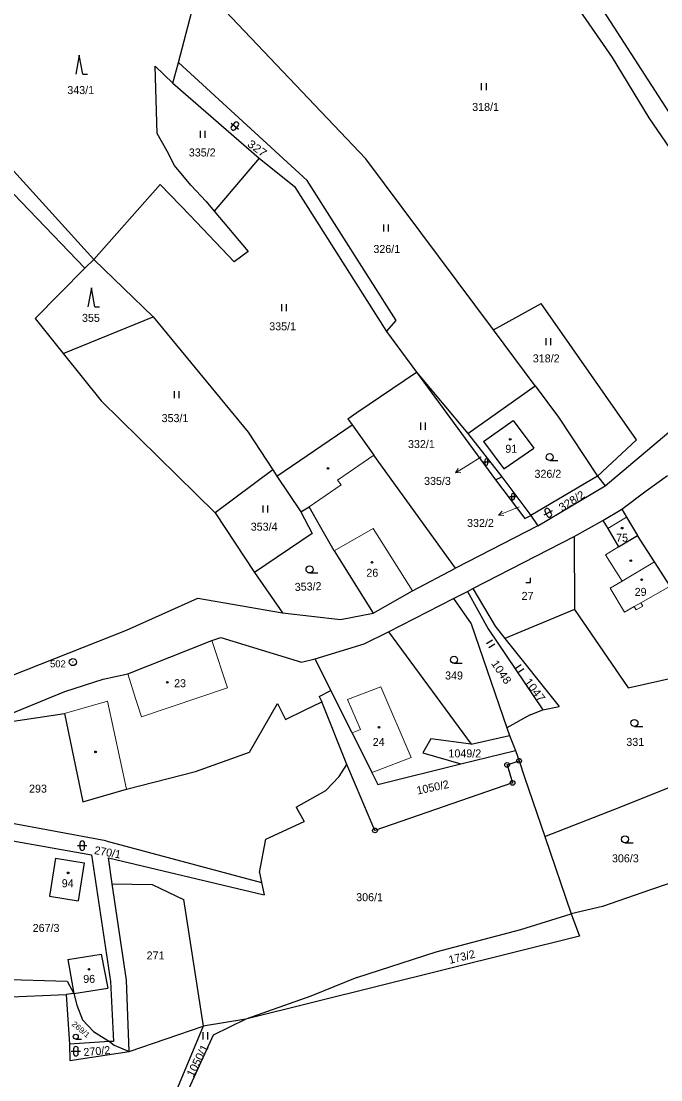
# Model space of a CAD drawing. Extents: x -744132 to -742433, y -984679 to -982287.
# Drawn here: x -742940.3 to -742804.5, y -984060.3 to -983835.5 of the extents above; entities that cross this region are included whole.
import ezdxf
from ezdxf.enums import TextEntityAlignment as Align

# ---------------------------------------------------------------- set-up
doc = ezdxf.new("R2010")
doc.units = 0
doc.header["$LTSCALE"] = 0.68
for name, color, linetype, lineweight in [('1', 7, 'Continuous', 25), ('3', 7, 'Continuous', 25), ('4', 7, 'Continuous', 13), ('5', 7, 'Continuous', 25), ('7', 7, 'Continuous', 13), ('8', 7, 'Continuous', 25)]:
    doc.layers.add(name, color=color, linetype=linetype, lineweight=lineweight)
doc.layers.add('2', color=7, linetype='Continuous')

msp = doc.modelspace()

# ---------------------------------------------------------------- linework, layer by layer
at = {"layer": '1'}
for p, q in [((-742906.93, -983844.32), (-742902.5, -983827.5)), ((-742902.5, -983827.5), (-742867.15, -983864.75)), ((-742822.34, -983832.43), (-742814.87, -983843.28)), ((-742911.42, -983859.4), (-742911.86, -983845.12)), ((-742911.86, -983845.12), (-742908.09, -983848.73)), ((-742908.09, -983848.73), (-742906.93, -983844.32)), ((-742879.59, -983869.35), (-742906.93, -983844.32)), ((-742908.09, -983848.73), (-742889.81, -983864.61)), ((-742957.02, -983850.8), (-742924.88, -983886.12)), ((-742958.15, -983855.44), (-742926.77, -983887.99)), ((-742909.3, -983863.15), (-742911.42, -983859.4)), ((-742907.74, -983866.2), (-742909.3, -983863.15)), ((-742889.81, -983864.61), (-742899.34, -983875.86)), ((-742889.81, -983864.61), (-742882.28, -983870.68)), ((-742840.06, -983901.1), (-742867.15, -983864.75)), ((-742904.28, -983870.35), (-742907.74, -983866.2)), ((-742860.67, -983899.08), (-742879.59, -983869.35)), ((-742924.88, -983886.12), (-742910.78, -983870.22)), ((-742910.78, -983870.22), (-742904.43, -983876.79)), ((-742901.02, -983873.87), (-742904.28, -983870.35)), ((-742882.28, -983870.68), (-742862.74, -983901.46)), ((-742901.02, -983873.87), (-742899.34, -983875.86)), ((-742895.09, -983886.66), (-742904.43, -983876.79)), ((-742899.34, -983875.86), (-742892.1, -983884.42)), ((-742892.1, -983884.42), (-742895.09, -983886.66)), ((-742926.77, -983887.99), (-742937.35, -983898.71)), ((-742924.88, -983886.12), (-742926.77, -983887.99)), ((-742924.88, -983886.12), (-742912.26, -983898.3)), ((-742840.06, -983901.1), (-742829.92, -983895.5)), ((-742809.68, -983924.43), (-742829.92, -983895.5)), ((-742937.35, -983898.71), (-742931.39, -983906.13)), ((-742931.39, -983906.13), (-742912.26, -983898.3)), ((-742912.26, -983898.3), (-742892.13, -983922.84)), ((-742862.74, -983901.46), (-742860.67, -983899.08)), ((-742862.74, -983901.46), (-742856.35, -983910.04)), ((-742831.22, -983912.97), (-742840.06, -983901.1)), ((-742931.39, -983906.13), (-742923.32, -983916.19)), ((-742869.02, -983918.66), (-742856.35, -983910.04)), ((-742856.35, -983910.04), (-742845.49, -983923.07)), ((-742856.35, -983910.04), (-742839.64, -983932.92)), ((-742845.49, -983923.07), (-742831.22, -983912.97)), ((-742831.22, -983912.97), (-742826.26, -983919.63)), ((-742923.32, -983916.19), (-742899.16, -983939.96)), ((-742870.96, -983919.98), (-742869.02, -983918.66)), ((-742886.03, -983932.15), (-742870.04, -983921.26)), ((-742870.96, -983919.98), (-742870.04, -983921.26)), ((-742870.04, -983921.26), (-742865.41, -983927.69)), ((-742842.15, -983924.76), (-742835.85, -983920.32)), ((-742835.85, -983920.32), (-742831.51, -983926.18)), ((-742826.26, -983919.63), (-742817.93, -983932.14)), ((-742816.35, -983934.19), (-742801.5, -983921.65)), ((-742892.13, -983922.84), (-742886.92, -983930.82)), ((-742845.49, -983923.07), (-742838.25, -983932.27)), ((-742842.15, -983924.76), (-742837.81, -983930.62)), ((-742837.81, -983930.62), (-742831.51, -983926.18)), ((-742817.93, -983932.14), (-742809.68, -983924.43)), ((-742848.1, -983951.72), (-742865.41, -983927.69)), ((-742886.92, -983930.82), (-742899.16, -983939.96)), ((-742886.92, -983930.82), (-742886.03, -983932.15)), ((-742886.03, -983932.15), (-742880.96, -983939.76)), ((-742839.64, -983932.92), (-742838.25, -983932.27)), ((-742839.64, -983932.92), (-742833.37, -983941.15)), ((-742838.25, -983932.27), (-742832.11, -983940.49)), ((-742817.93, -983932.14), (-742832.11, -983940.49)), ((-742817.93, -983932.14), (-742816.35, -983934.19)), ((-742807.62, -983935.3), (-742803.12, -983932.02)), ((-742830.62, -983942.7), (-742816.35, -983934.19)), ((-742812.81, -983939.15), (-742807.62, -983935.3)), ((-742880.96, -983939.76), (-742879.2, -983938.64)), ((-742880.96, -983939.76), (-742878.57, -983944.32)), ((-742876.73, -983943.06), (-742879.2, -983938.64)), ((-742816.81, -983941.55), (-742812.81, -983939.15)), ((-742812.81, -983939.15), (-742811.81, -983940.86)), ((-742899.16, -983939.96), (-742890.8, -983952.62)), ((-742833.37, -983941.15), (-742832.11, -983940.49)), ((-742832.11, -983940.49), (-742830.62, -983942.7)), ((-742822.88, -983944.99), (-742816.81, -983941.55)), ((-742816.81, -983941.55), (-742815.8, -983943.23)), ((-742811.81, -983940.86), (-742809.44, -983944.76)), ((-742873.89, -983948.03), (-742876.73, -983943.06)), ((-742830.62, -983942.7), (-742848.1, -983951.72)), ((-742815.8, -983943.23), (-742813.47, -983947.16)), ((-742844.42, -983956.03), (-742822.88, -983944.99)), ((-742822.88, -983944.99), (-742822.83, -983960.49)), ((-742813.47, -983947.16), (-742809.44, -983944.76)), ((-742805.85, -983950.36), (-742809.44, -983944.76)), ((-742873.89, -983948.03), (-742865.57, -983961.25)), ((-742802.53, -983955.53), (-742805.85, -983950.36)), ((-742857.26, -983956.51), (-742848.1, -983951.72)), ((-742865.57, -983961.25), (-742857.26, -983956.51)), ((-742848.52, -983958.12), (-742845.59, -983956.63)), ((-742845.59, -983956.63), (-742844.42, -983956.03)), ((-742845.59, -983956.63), (-742841.2, -983964.6)), ((-742844.42, -983956.03), (-742839.7, -983963.97)), ((-742917.94, -983964.86), (-742902.8, -983958.08)), ((-742902.8, -983958.08), (-742884.85, -983961.14)), ((-742862.31, -983965.19), (-742848.52, -983958.12)), ((-742848.52, -983958.12), (-742844.8, -983963.48)), ((-742884.85, -983961.14), (-742872.49, -983962.57)), ((-742872.49, -983962.57), (-742865.57, -983961.25)), ((-742822.83, -983960.49), (-742837.61, -983966.59)), ((-742822.83, -983960.49), (-742811.46, -983977.13)), ((-742844.8, -983963.48), (-742837.22, -983985.6)), ((-742839.7, -983963.97), (-742837.61, -983966.59)), ((-742945.7, -983975.78), (-742917.94, -983964.86)), ((-742899.86, -983967.08), (-742897.96, -983966.39)), ((-742897.96, -983966.39), (-742880.79, -983971.66)), ((-742867.51, -983967.72), (-742862.31, -983965.19)), ((-742862.31, -983965.19), (-742844.76, -983989.03)), ((-742841.2, -983964.6), (-742829.58, -983981.79)), ((-742837.61, -983966.59), (-742826.07, -983981.08)), ((-742917.66, -983974.14), (-742899.86, -983967.08)), ((-742877.9, -983970.94), (-742867.51, -983967.72)), ((-742880.79, -983971.66), (-742877.9, -983970.94)), ((-742874.54, -983977.66), (-742877.9, -983970.94)), ((-742931.01, -983977.85), (-742922.89, -983975.29)), ((-742922.89, -983975.29), (-742917.66, -983974.14)), ((-742811.46, -983977.13), (-742801.02, -983974.74)), ((-742954.25, -983987.39), (-742931.01, -983977.85)), ((-742877.04, -983978.95), (-742874.54, -983977.66)), ((-742870.05, -983986.66), (-742874.54, -983977.66)), ((-742880.19, -983981.86), (-742876.47, -983980.05)), ((-742877.04, -983978.95), (-742876.47, -983980.05)), ((-742871.15, -983993.39), (-742876.47, -983980.05)), ((-742943.85, -983984.44), (-742931.13, -983982.52)), ((-742931.13, -983982.52), (-742927.2, -984001.32)), ((-742891.86, -983990.76), (-742885.87, -983980.42)), ((-742885.87, -983980.42), (-742884.21, -983983.82)), ((-742884.21, -983983.82), (-742880.19, -983981.86)), ((-742832.26, -983982.86), (-742829.58, -983981.79)), ((-742829.58, -983981.79), (-742826.07, -983981.08)), ((-742832.26, -983982.86), (-742837.22, -983985.6)), ((-742870.05, -983986.66), (-742865.86, -983995.06)), ((-742837.22, -983985.6), (-742836.67, -983987.2)), ((-742853.34, -983987.9), (-742855.06, -983990.91)), ((-742844.76, -983989.03), (-742853.34, -983987.9)), ((-742844.76, -983989.03), (-742836.67, -983987.2)), ((-742836.67, -983987.2), (-742835.34, -983990.38)), ((-742903.31, -983994.88), (-742891.86, -983990.76)), ((-742855.06, -983990.91), (-742846.99, -983993.21)), ((-742846.99, -983993.21), (-742835.34, -983990.38)), ((-742835.34, -983990.38), (-742834.61, -983992.59)), ((-742872.82, -983995.92), (-742871.15, -983993.39)), ((-742869.15, -983998.19), (-742871.15, -983993.39)), ((-742864.57, -983997.65), (-742846.99, -983993.21)), ((-742837.15, -983993.45), (-742834.61, -983992.59)), ((-742837.15, -983993.45), (-742835.99, -983997.29)), ((-742834.61, -983992.59), (-742833.48, -983996.03)), ((-742917.96, -983998.64), (-742903.31, -983994.88)), ((-742875.66, -983998.9), (-742872.82, -983995.92)), ((-742865.86, -983995.06), (-742864.57, -983997.65)), ((-742833.48, -983996.03), (-742829.17, -984008.67)), ((-742812.62, -984002.25), (-742792.81, -983994.21)), ((-742865.2, -984007.38), (-742869.15, -983998.19)), ((-742835.99, -983997.29), (-742865.2, -984007.38)), ((-742927.2, -984001.32), (-742917.96, -983998.64)), ((-742881.96, -984002.42), (-742875.66, -983998.9)), ((-742881.96, -984002.42), (-742880.25, -984005.47)), ((-742829.17, -984008.67), (-742812.62, -984002.25)), ((-742922.34, -984009.55), (-742943.7, -984005.59)), ((-742888.35, -984009.24), (-742880.25, -984005.47)), ((-742889.73, -984016.32), (-742888.35, -984009.24)), ((-742829.17, -984008.67), (-742823.57, -984025.07)), ((-742942.1, -984009.55), (-742925.39, -984012.53)), ((-742922.34, -984009.55), (-742889.28, -984018.41)), ((-742933, -984013.29), (-742934.28, -984021.31)), ((-742933, -984013.29), (-742926.93, -984014.28)), ((-742925.39, -984012.53), (-742921.36, -984039.47)), ((-742921.8, -984013.22), (-742888.71, -984021.05)), ((-742920.98, -984018.74), (-742921.8, -984013.22)), ((-742786.48, -984013.12), (-742806.72, -984019.96)), ((-742926.93, -984014.28), (-742928.22, -984022.3)), ((-742889.73, -984016.32), (-742889.28, -984018.41)), ((-742889.28, -984018.41), (-742888.71, -984021.05)), ((-742917.95, -984039.15), (-742920.98, -984018.74)), ((-742920.98, -984018.74), (-742912.47, -984018.85)), ((-742912.47, -984018.85), (-742905.85, -984022.02)), ((-742806.72, -984019.96), (-742816.93, -984023.51)), ((-742934.28, -984021.31), (-742928.22, -984022.3)), ((-742905.85, -984022.02), (-742901.65, -984048.94)), ((-742834.23, -984028.38), (-742823.57, -984025.07)), ((-742816.93, -984023.51), (-742823.57, -984025.07)), ((-742823.57, -984025.07), (-742821.81, -984029.84)), ((-742852.2, -984033.16), (-742834.23, -984028.38)), ((-742821.81, -984029.84), (-742892.62, -984047.46)), ((-742930.4, -984034.77), (-742923.31, -984033.62)), ((-742923.31, -984033.62), (-742921.95, -984040.84)), ((-742869.08, -984038.63), (-742852.2, -984033.16)), ((-742930.4, -984034.77), (-742929.11, -984041.97)), ((-742869.08, -984038.63), (-742878.81, -984042.59)), ((-742945.1, -984038.93), (-742930.55, -984039.41)), ((-742930.55, -984039.41), (-742929.11, -984041.97)), ((-742929.11, -984041.97), (-742921.95, -984040.84)), ((-742921.36, -984039.47), (-742920.74, -984052.2)), ((-742917.4, -984054.33), (-742917.95, -984039.15)), ((-742944.15, -984042.77), (-742930.74, -984042.18)), ((-742929.11, -984041.97), (-742930.74, -984042.18)), ((-742930.74, -984042.18), (-742930.03, -984052.75)), ((-742929.11, -984041.97), (-742928.47, -984044.46)), ((-742878.81, -984042.59), (-742892.62, -984047.46)), ((-742928.47, -984044.46), (-742927.27, -984047.62)), ((-742927.27, -984047.62), (-742924.96, -984050.04)), ((-742892.62, -984047.46), (-742901.65, -984048.94)), ((-742892.62, -984047.46), (-742899.55, -984050.85)), ((-742917.4, -984054.33), (-742901.65, -984048.94)), ((-742901.65, -984048.94), (-742915.06, -984080.88)), ((-742921.57, -984052.19), (-742930.03, -984052.75)), ((-742899.55, -984050.85), (-742927.66, -984112.13)), ((-742924.96, -984050.04), (-742922.72, -984051.45)), ((-742922.72, -984051.45), (-742921.57, -984052.19)), ((-742921.57, -984052.19), (-742920.54, -984052.96)), ((-742920.74, -984052.2), (-742921.57, -984052.19)), ((-742930.03, -984052.75), (-742930, -984056.21)), ((-742930, -984056.21), (-742917.4, -984054.33)), ((-742920.54, -984052.96), (-742917.4, -984054.33))]:
    msp.add_line(p, q, dxfattribs=at)
for points in [[(-742790.13, -983873.29), (-742800.65, -983858.18), (-742818.84, -983829.92)], [(-742814.87, -983843.28), (-742807.06, -983856.08), (-742800.89, -983865.04)], [(-742878.57, -983944.32), (-742890.8, -983952.62), (-742884.85, -983961.14)]]:
    msp.add_lwpolyline(points, dxfattribs=at)
at = {"layer": '3'}
for p, q in [((-742927.23, -983846.78), (-742926.234, -983846.78)), ((-742842.551, -983850.21), (-742842.551, -983848.71)), ((-742841.55, -983850.21), (-742841.55, -983848.71)), ((-742902.241, -983860.34), (-742902.241, -983858.84)), ((-742901.24, -983860.34), (-742901.24, -983858.84)), ((-742895.7, -983857.169), (-742894.189, -983858.483)), ((-742894.994, -983857.12), (-742895.651, -983857.876)), ((-742894.895, -983858.532), (-742894.238, -983857.777)), ((-742863.331, -983880.19), (-742863.331, -983878.69)), ((-742862.33, -983880.19), (-742862.33, -983878.69)), ((-742924.65, -983896.17), (-742923.654, -983896.17)), ((-742884.961, -983897.13), (-742884.961, -983895.63)), ((-742883.96, -983897.13), (-742883.96, -983895.63)), ((-742828.891, -983904.32), (-742828.891, -983902.82)), ((-742827.89, -983904.32), (-742827.89, -983902.82)), ((-742907.751, -983915.59), (-742907.751, -983914.09)), ((-742906.75, -983915.59), (-742906.75, -983914.09)), ((-742855.471, -983922.29), (-742855.471, -983920.79)), ((-742854.47, -983922.29), (-742854.47, -983920.79)), ((-742842.221, -983929.141), (-742840.879, -983929.141)), ((-742841.885, -983928.805), (-742841.885, -983929.476)), ((-742841.215, -983929.476), (-742841.215, -983928.805)), ((-742828.103, -983928.85), (-742826.353, -983928.85)), ((-742836.571, -983936.491), (-742835.229, -983936.491)), ((-742836.235, -983936.155), (-742836.235, -983936.826)), ((-742835.565, -983936.826), (-742835.565, -983936.155)), ((-742888.931, -983939.89), (-742888.931, -983938.39)), ((-742887.93, -983939.89), (-742887.93, -983938.39)), ((-742829.293, -983940.388), (-742827.525, -983939.448)), ((-742829.086, -983939.711), (-742828.616, -983940.595)), ((-742827.732, -983940.125), (-742828.202, -983939.241)), ((-742879.083, -983952.71), (-742877.333, -983952.71)), ((-742841.533, -983967.672), (-742840.247, -983966.9)), ((-742841.017, -983968.53), (-742839.732, -983967.758)), ((-742848.413, -983971.89), (-742846.663, -983971.89)), ((-742835.408, -983972.982), (-742834.15, -983972.165)), ((-742834.863, -983973.821), (-742833.605, -983973.004)), ((-742810.113, -983985.3), (-742808.363, -983985.3)), ((-742928.341, -984010.601), (-742926.339, -984010.601)), ((-742927.841, -984010.101), (-742927.841, -984011.102)), ((-742926.839, -984011.102), (-742926.839, -984010.101)), ((-742812.123, -984010.01), (-742810.373, -984010.01)), ((-742928.715, -984051.69), (-742927.49, -984051.69)), ((-742901.661, -984051.73), (-742901.661, -984050.23)), ((-742900.66, -984051.73), (-742900.66, -984050.23)), ((-742929.701, -984054.251), (-742927.699, -984054.251)), ((-742929.201, -984053.751), (-742929.201, -984054.752)), ((-742928.199, -984054.752), (-742928.199, -984053.751))]:
    msp.add_line(p, q, dxfattribs=at)
for points in [[(-742927.23, -983846.78), (-742927.98, -983842.78), (-742928.73, -983846.78)], [(-742924.65, -983896.17), (-742925.4, -983892.17), (-742926.15, -983896.17)], [(-742833.201, -983954.75), (-742832.2, -983954.75), (-742832.2, -983953.75)]]:
    msp.add_lwpolyline(points, dxfattribs=at)
for centre, radius in [((-742828.1029, -983928.0998), 0.75), ((-742879.0829, -983951.9598), 0.75), ((-742848.4129, -983971.1398), 0.75), ((-742810.1129, -983984.5498), 0.75), ((-742812.1229, -984009.2598), 0.75), ((-742928.715, -984051.1649), 0.525)]:
    msp.add_circle(centre, radius, dxfattribs=at)
for centre, radius, start, end in [((-742895.2726, -983858.2033), 0.5, 139, 318.98789), ((-742894.6165, -983857.4486), 0.5, 319, 139), ((-742841.55, -983928.8056), 0.335, 0, 180), ((-742841.55, -983929.4756), 0.335, 180, 359.98789), ((-742835.9, -983936.1556), 0.335, 0, 180), ((-742835.9, -983936.8256), 0.335, 180, 359.98789), ((-742828.6438, -983939.4764), 0.5, 28, 208), ((-742828.1743, -983940.3593), 0.5, 208, 27.98789), ((-742927.34, -984010.1009), 0.5, 0, 180), ((-742927.34, -984011.1009), 0.5, 180, 359.98789), ((-742928.7, -984053.7509), 0.5, 0, 180), ((-742928.7, -984054.7509), 0.5, 180, 359.98789)]:
    msp.add_arc(centre, radius, start, end, dxfattribs=at)
at = {"layer": '4'}
for p, q in [((-742873.19, -983932.97), (-742865.41, -983927.69)), ((-742872.36, -983934.01), (-742873.19, -983932.97)), ((-742879.2, -983938.64), (-742872.36, -983934.01)), ((-742815.8, -983943.23), (-742811.81, -983940.86)), ((-742873.89, -983948.03), (-742865.58, -983943.29)), ((-742865.58, -983943.29), (-742857.26, -983956.51)), ((-742813.47, -983947.16), (-742816.28, -983948.83)), ((-742812.69, -983954.43), (-742816.28, -983948.83)), ((-742805.85, -983950.36), (-742812.69, -983954.43)), ((-742812.69, -983954.43), (-742815.27, -983955.96)), ((-742808.73, -983959.04), (-742802.53, -983955.53)), ((-742808.73, -983959.04), (-742810.16, -983959.85)), ((-742899.86, -983967.08), (-742896.52, -983977.11)), ((-742917.66, -983974.14), (-742916.04, -983979.35)), ((-742914.79, -983983.23), (-742896.52, -983977.11)), ((-742871.01, -983979.59), (-742863.93, -983976.87)), ((-742863.93, -983976.87), (-742857.53, -983991.86)), ((-742931.13, -983982.52), (-742922.02, -983979.91)), ((-742917.96, -983998.64), (-742922.02, -983979.91)), ((-742916.04, -983979.35), (-742915.76, -983980.24)), ((-742915.76, -983980.24), (-742914.79, -983983.23)), ((-742871.01, -983979.59), (-742868.25, -983985.97)), ((-742870.05, -983986.66), (-742868.25, -983985.97)), ((-742864.54, -983994.55), (-742857.53, -983991.86)), ((-742865.86, -983995.06), (-742864.54, -983994.55))]:
    msp.add_line(p, q, dxfattribs=at)
for points in [[(-742815.27, -983955.96), (-742812.25, -983961.03), (-742810.16, -983959.85)], [(-742810.16, -983959.85), (-742809.77, -983960.54), (-742808.33, -983959.73), (-742808.73, -983959.04)]]:
    msp.add_lwpolyline(points, dxfattribs=at)
at = {"layer": '5'}
for centre in [(-742836.4868, -983924.3492), (-742875.1568, -983930.5192), (-742812.7368, -983943.1892), (-742865.8468, -983950.4392), (-742810.8968, -983950.0792), (-742808.5868, -983954.1392), (-742909.2868, -983975.9192), (-742864.3468, -983985.4492), (-742924.5168, -983990.6892), (-742930.3468, -984016.3892), (-742925.9268, -984036.8592)]:
    msp.add_circle(centre, 0.175, dxfattribs=at)
at = {"layer": '7'}
for p, q in [((-742848.095, -983931.45), (-742846.98, -983931.344)), ((-742838.952, -983940.414), (-742837.836, -983940.503))]:
    msp.add_line(p, q, dxfattribs=at)
for points in [[(-742842.64, -983928.05), (-742845.55, -983929.86), (-742848.095, -983931.45), (-742847.511, -983930.495)], [(-742834.58, -983938.65), (-742836.17, -983939.29), (-742838.952, -983940.414), (-742838.212, -983939.575)]]:
    msp.add_lwpolyline(points, dxfattribs=at)
at = {"layer": '8'}
for centre, radius in [((-742929.34, -983971.6298), 0.75), ((-742929.34, -983971.6298), 0.03), ((-742837.15, -983993.4499), 0.5), ((-742837.15, -983993.4499), 0.0303), ((-742834.61, -983992.5899), 0.5), ((-742834.61, -983992.5899), 0.0303), ((-742835.99, -983997.2899), 0.5), ((-742835.99, -983997.2899), 0.0303), ((-742865.2, -984007.3799), 0.5), ((-742865.2, -984007.3799), 0.0303)]:
    msp.add_circle(centre, radius, dxfattribs=at)

# ---------------------------------------------------------------- texts
at = {"layer": '2'}
for s, p in [('343/1', (-742930.52, -983851.025)), ('335/2', (-742904.72, -983864.275)), ('326/1', (-742865.54, -983884.765)), ('355', (-742927.4, -983899.395)), ('335/1', (-742887.65, -983901.185)), ('353/1', (-742910.5, -983920.675)), ('332/1', (-742858.19, -983926.185)), ('91', (-742837.53, -983927.185)), ('326/2', (-742831.34, -983932.505)), ('353/4', (-742891.58, -983943.735)), ('75', (-742814.01, -983946.075)), ('26', (-742867.03, -983953.515)), ('27', (-742834.07, -983958.425)), ('29', (-742810.07, -983957.575)), ('23', (-742907.85, -983976.965)), ('349', (-742850.32, -983975.325)), ('24', (-742865.68, -983989.435)), ('331', (-742811.84, -983989.425)), ('1049/2', (-742849.6, -983991.865)), ('293', (-742938.64, -983999.345)), ('306/3', (-742814.89, -984014.145)), ('94', (-742931.7, -984019.435)), ('306/1', (-742869.19, -984022.395)), ('267/3', (-742937.87, -984028.925)), ('271', (-742913.68, -984034.775)), ('96', (-742927.14, -984039.745))]:
    msp.add_text(s, height=1.7, dxfattribs=at).set_placement(p)
for s, p in [('318/1', (-742841.72, -983854.605)), ('318/2', (-742828.85, -983907.995))]:
    msp.add_text(s, height=1.7, dxfattribs=at).set_placement(p, align=Align.CENTER)
for s, height, rotation, width, p in [('327', 1.7, 324, 1.15, (-742892.469, -983861.963)), ('328/2', 1.7, 32, 1.05, (-742825.514, -983939.71)), ('1048', 1.7, 304, 1.1, (-742840.622, -983971.907)), ('1047', 1.7, 307, 1.1, (-742833.609, -983975.835)), ('269/1', 1.19, 320, 1.1, (-742929.701, -984048.667)), ('1050/1', 1.7, 63, 1.05, (-742903.781, -984059.892))]:
    msp.add_text(s, height=height, rotation=rotation, dxfattribs=dict(at, width=width)).set_placement(p)
for s, p in [('335/3', (-742849.09, -983934.015)), ('332/2', (-742839.96, -983942.935))]:
    msp.add_text(s, height=1.7, dxfattribs=at).set_placement(p, align=Align.RIGHT)
for s, rotation, p in [('353/2', 2, (-742882.205, -983956.534)), ('1050/2', 12, (-742856.161, -983999.765)), ('270/1', 350, (-742924.893, -984012.358)), ('173/2', 14, (-742849.317, -984035.722)), ('270/2', 5, (-742927.012, -984055.313))]:
    msp.add_text(s, height=1.7, rotation=rotation, dxfattribs=at).set_placement(p)
at = {"layer": '8'}
msp.add_text('502', height=1.5, dxfattribs=at).set_placement((-742930.839, -983972.747), align=Align.RIGHT)

doc.saveas('drawing.dxf')
